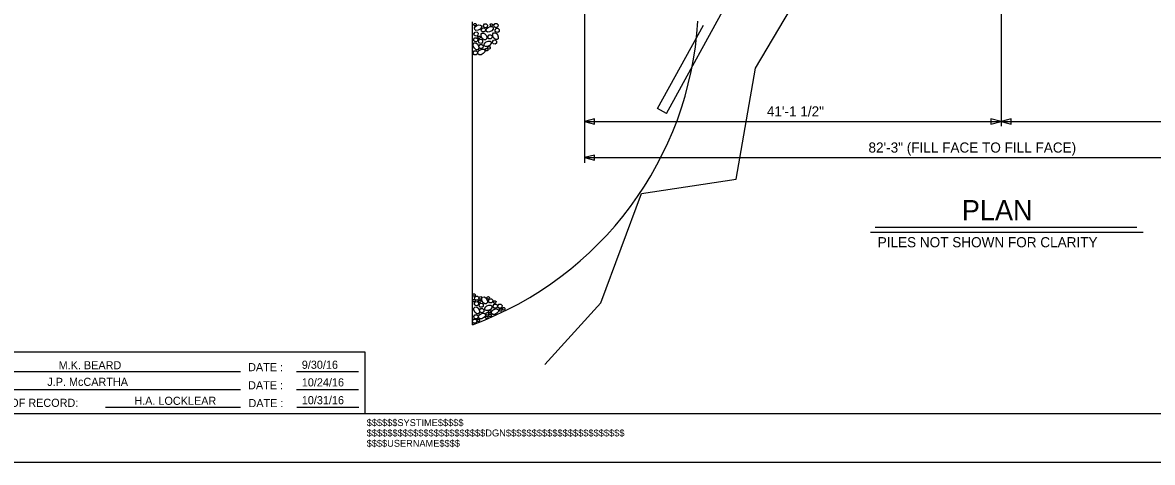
# Model space of a CAD drawing. Extents: x 471 to 2034, y -623 to 126.
# Drawn here: x 1490.5 to 1602, y -95.1 to -51.7 of the extents above; entities that cross this region are included whole.
import ezdxf

# ---------------------------------------------------------------- set-up
doc = ezdxf.new("R2010")
doc.units = 0
for name, color, linetype in [('Auto Dimensioning', 7, 'Continuous'), ('Dimension Lines', 7, 'Continuous'), ('Exist Hydro Stream or Body of Water', 7, 'Continuous'), ('Exist Structure Major Bridge Seam', 7, 'Continuous'), ('Miscellaneous Lines CELL', 7, 'Continuous'), ('Plan Sheet CELL', 7, 'Continuous'), ('Plot Label CELL', 7, 'Continuous'), ('Plot Shape CELL', 7, 'Continuous'), ('Sub End Bent Cap Lines CELL', 7, 'Continuous'), ('Subtitle Text', 7, 'Continuous'), ('Sup Concrete Girder Lines', 7, 'Continuous'), ('Text', 7, 'Continuous'), ('Title Text', 7, 'Continuous')]:
    doc.layers.add(name, color=color, linetype=linetype)

# ---------------------------------------------------------------- blocks, each defined once
blk = doc.blocks.new('AH')
at = {"layer": 'Sub End Bent Cap Lines CELL'}
blk.add_lwpolyline([(0, 0), (-1.25, 0.31), (-1.25, -0.31)], close=True, dxfattribs=at)

msp = doc.modelspace()

# ---------------------------------------------------------------- linework, layer by layer
at = {"layer": 'Auto Dimensioning'}
for p, q in [((1545.96, -33.72), (1545.96, -65.55)), ((1545.96, -61.48), (1587.08, -61.48)), ((1587.08, -61.48), (1628.19, -61.48)), ((1545.96, -65.05), (1628.19, -65.05))]:
    msp.add_line(p, q, dxfattribs=at)
at = {"layer": 'Dimension Lines'}
msp.add_line((1587.08, -33.22), (1587.08, -61.95), dxfattribs=at)
at = {"layer": 'Exist Hydro Stream or Body of Water'}
for points in [[(1562.84, -56.21), (1566.3, -50.38), (1560.81, -40.91)], [(1542.05, -85.49), (1547.57, -79.39), (1551.61, -68.59), (1560.94, -67.16), (1562.84, -56.21)]]:
    msp.add_lwpolyline(points, dxfattribs=at)
at = {"layer": 'Exist Structure Major Bridge Seam'}
for p, q in [((1554.07, -60.68), (1560.64, -48.7)), ((1553.19, -60.2), (1557.72, -51.96)), ((1554.07, -60.68), (1553.19, -60.2))]:
    msp.add_line(p, q, dxfattribs=at)
at = {"layer": 'Miscellaneous Lines CELL'}
for points in [[(1535.03, -51.89), (1535.1, -51.79), (1535.21, -51.79), (1535.28, -51.86), (1535.27, -51.97), (1535.2, -52.03), (1535.1, -52.02), (1535.05, -51.97), (1535.03, -51.89)], [(1535.32, -52.01), (1535.53, -51.93), (1535.72, -51.95), (1535.82, -52.03), (1535.81, -52.19), (1535.67, -52.37), (1535.46, -52.47), (1535.26, -52.48), (1535.14, -52.4), (1535.13, -52.23), (1535.22, -52.09), (1535.33, -52.01)], [(1535.78, -52.41), (1535.89, -52.25), (1536.07, -52.24), (1536.19, -52.37), (1536.17, -52.55), (1536.06, -52.64), (1535.89, -52.63), (1535.8, -52.55), (1535.78, -52.41)], [(1535.99, -51.99), (1536.1, -51.83), (1536.28, -51.82), (1536.4, -51.95), (1536.38, -52.13), (1536.27, -52.22), (1536.1, -52.21), (1536.01, -52.13), (1535.99, -51.99)], [(1536.46, -52.18), (1536.67, -52.1), (1536.86, -52.11), (1536.95, -52.2), (1536.95, -52.36), (1536.81, -52.54), (1536.6, -52.64), (1536.4, -52.65), (1536.28, -52.57), (1536.27, -52.4), (1536.36, -52.26), (1536.47, -52.18)], [(1536.67, -51.93), (1536.73, -51.83), (1536.84, -51.82), (1536.92, -51.9), (1536.9, -52.01), (1536.84, -52.06), (1536.73, -52.06), (1536.68, -52.01), (1536.67, -51.93)], [(1537.03, -51.97), (1537.15, -51.81), (1537.32, -51.8), (1537.45, -51.93), (1537.43, -52.11), (1537.32, -52.2), (1537.14, -52.19), (1537.06, -52.11), (1537.03, -51.97)], [(1537.14, -52.44), (1537.25, -52.28), (1537.43, -52.27), (1537.55, -52.4), (1537.54, -52.58), (1537.43, -52.68), (1537.25, -52.66), (1537.17, -52.58), (1537.14, -52.44)], [(1535.03, -53.37), (1535.14, -53.21), (1535.32, -53.2), (1535.44, -53.33), (1535.42, -53.51), (1535.31, -53.6), (1535.14, -53.59), (1535.05, -53.5), (1535.03, -53.37)], [(1535.06, -52.81), (1535.17, -52.65), (1535.35, -52.64), (1535.47, -52.77), (1535.45, -52.95), (1535.34, -53.04), (1535.17, -53.03), (1535.08, -52.95), (1535.06, -52.81)], [(1535.44, -53.14), (1535.51, -53.04), (1535.62, -53.04), (1535.69, -53.11), (1535.68, -53.22), (1535.61, -53.28), (1535.51, -53.27), (1535.46, -53.22), (1535.44, -53.14)], [(1535.5, -53.52), (1535.61, -53.37), (1535.79, -53.35), (1535.91, -53.48), (1535.9, -53.66), (1535.79, -53.76), (1535.61, -53.74), (1535.53, -53.66), (1535.5, -53.52)], [(1536.23, -52.93), (1536.32, -53.13), (1536.3, -53.33), (1536.21, -53.42), (1536.06, -53.42), (1535.88, -53.28), (1535.77, -53.06), (1535.77, -52.86), (1535.85, -52.75), (1536.01, -52.74), (1536.15, -52.83), (1536.24, -52.93)], [(1536.43, -53.08), (1536.55, -52.92), (1536.73, -52.91), (1536.85, -53.04), (1536.83, -53.22), (1536.72, -53.32), (1536.54, -53.3), (1536.46, -53.22), (1536.43, -53.08)], [(1536.88, -53.6), (1536.99, -53.44), (1537.17, -53.43), (1537.3, -53.56), (1537.28, -53.74), (1537.17, -53.84), (1536.99, -53.82), (1536.91, -53.74), (1536.88, -53.6)], [(1537.37, -52.9), (1537.45, -53.11), (1537.44, -53.3), (1537.35, -53.39), (1537.19, -53.39), (1537.02, -53.25), (1536.91, -53.04), (1536.91, -52.83), (1536.99, -52.72), (1537.15, -52.71), (1537.29, -52.8), (1537.38, -52.91)], [(1534.98, -54.67), (1535.09, -54.51), (1535.27, -54.5), (1535.4, -54.62), (1535.38, -54.81), (1535.27, -54.9), (1535.09, -54.88), (1535.01, -54.8), (1534.98, -54.67)], [(1535.45, -53.9), (1535.54, -54.11), (1535.52, -54.3), (1535.43, -54.4), (1535.28, -54.39), (1535.1, -54.25), (1534.99, -54.04), (1534.99, -53.84), (1535.07, -53.72), (1535.23, -53.71), (1535.37, -53.8), (1535.46, -53.91)], [(1535.63, -54.42), (1535.84, -54.34), (1536.03, -54.35), (1536.12, -54.44), (1536.12, -54.6), (1535.98, -54.77), (1535.76, -54.88), (1535.56, -54.88), (1535.45, -54.8), (1535.44, -54.64), (1535.53, -54.5), (1535.64, -54.41)], [(1535.55, -54.05), (1535.66, -53.89), (1535.84, -53.88), (1535.96, -54.01), (1535.95, -54.19), (1535.84, -54.28), (1535.66, -54.27), (1535.58, -54.19), (1535.55, -54.05)], [(1536.26, -53.62), (1536.47, -53.53), (1536.66, -53.55), (1536.75, -53.64), (1536.75, -53.79), (1536.61, -53.97), (1536.39, -54.08), (1536.19, -54.08), (1536.08, -54), (1536.07, -53.84), (1536.16, -53.7), (1536.27, -53.61)], [(1536.18, -54.37), (1536.24, -54.28), (1536.35, -54.27), (1536.43, -54.35), (1536.42, -54.46), (1536.35, -54.51), (1536.24, -54.51), (1536.19, -54.46), (1536.18, -54.37)], [(1536.41, -54.18), (1536.48, -54.08), (1536.58, -54.08), (1536.66, -54.16), (1536.65, -54.26), (1536.58, -54.32), (1536.47, -54.31), (1536.42, -54.26), (1536.41, -54.18)], [(1534.93, -78.59), (1535, -78.49), (1535.11, -78.49), (1535.18, -78.56), (1535.17, -78.67), (1535.11, -78.73), (1535, -78.72), (1534.95, -78.67), (1534.93, -78.59)], [(1534.93, -79.15), (1535, -79.06), (1535.11, -79.05), (1535.18, -79.13), (1535.17, -79.24), (1535.11, -79.29), (1535, -79.29), (1534.95, -79.24), (1534.93, -79.15)], [(1535.13, -78.89), (1535.24, -78.73), (1535.42, -78.72), (1535.54, -78.85), (1535.52, -79.03), (1535.41, -79.12), (1535.24, -79.11), (1535.15, -79.03), (1535.13, -78.89)], [(1535.51, -79.21), (1535.58, -79.12), (1535.69, -79.11), (1535.76, -79.19), (1535.75, -79.3), (1535.68, -79.35), (1535.58, -79.35), (1535.53, -79.3), (1535.51, -79.21)], [(1535.57, -78.87), (1535.64, -78.78), (1535.74, -78.77), (1535.82, -78.85), (1535.81, -78.96), (1535.74, -79.01), (1535.63, -79.01), (1535.58, -78.96), (1535.57, -78.87)], [(1536.3, -79), (1536.39, -79.21), (1536.37, -79.4), (1536.28, -79.49), (1536.13, -79.49), (1535.95, -79.35), (1535.84, -79.14), (1535.84, -78.93), (1535.92, -78.82), (1536.08, -78.81), (1536.22, -78.9), (1536.31, -79.01)], [(1536.33, -78.87), (1536.4, -78.78), (1536.51, -78.77), (1536.58, -78.85), (1536.57, -78.96), (1536.5, -79.01), (1536.4, -79.01), (1536.35, -78.96), (1536.33, -78.87)], [(1536.5, -79.16), (1536.62, -79), (1536.79, -78.99), (1536.92, -79.12), (1536.9, -79.3), (1536.79, -79.39), (1536.61, -79.38), (1536.53, -79.3), (1536.5, -79.16)], [(1535.52, -79.98), (1535.61, -80.19), (1535.59, -80.38), (1535.5, -80.47), (1535.35, -80.47), (1535.17, -80.33), (1535.06, -80.11), (1535.06, -79.91), (1535.14, -79.8), (1535.3, -79.79), (1535.44, -79.88), (1535.53, -79.98)], [(1535.09, -79.44), (1535.21, -79.28), (1535.39, -79.27), (1535.51, -79.4), (1535.49, -79.58), (1535.38, -79.67), (1535.21, -79.66), (1535.12, -79.58), (1535.1, -79.44)], [(1535.57, -79.6), (1535.68, -79.44), (1535.86, -79.43), (1535.98, -79.56), (1535.97, -79.74), (1535.86, -79.83), (1535.68, -79.82), (1535.6, -79.74), (1535.57, -79.6)], [(1535.62, -80.12), (1535.73, -79.96), (1535.91, -79.95), (1536.03, -80.08), (1536.02, -80.26), (1535.9, -80.36), (1535.73, -80.34), (1535.65, -80.26), (1535.62, -80.12)], [(1536.33, -79.69), (1536.54, -79.61), (1536.73, -79.63), (1536.82, -79.71), (1536.82, -79.87), (1536.68, -80.05), (1536.46, -80.15), (1536.26, -80.16), (1536.15, -80.08), (1536.14, -79.92), (1536.23, -79.77), (1536.34, -79.69)], [(1536.48, -80.25), (1536.55, -80.16), (1536.65, -80.15), (1536.73, -80.23), (1536.72, -80.34), (1536.65, -80.39), (1536.54, -80.39), (1536.49, -80.34), (1536.48, -80.25)], [(1536.98, -80.07), (1537.19, -79.98), (1537.38, -80), (1537.47, -80.09), (1537.47, -80.24), (1537.33, -80.42), (1537.11, -80.53), (1536.91, -80.53), (1536.8, -80.45), (1536.79, -80.29), (1536.88, -80.15), (1536.99, -80.06)], [(1536.95, -79.68), (1537.06, -79.52), (1537.24, -79.51), (1537.37, -79.64), (1537.35, -79.82), (1537.24, -79.91), (1537.06, -79.9), (1536.98, -79.82), (1536.95, -79.68)], [(1536.99, -79.29), (1537.05, -79.19), (1537.16, -79.18), (1537.24, -79.26), (1537.23, -79.37), (1537.16, -79.43), (1537.05, -79.42), (1537, -79.37), (1536.99, -79.29)], [(1537.41, -79.68), (1537.53, -79.53), (1537.7, -79.52), (1537.83, -79.64), (1537.81, -79.82), (1537.7, -79.92), (1537.52, -79.9), (1537.44, -79.82), (1537.41, -79.68)], [(1537.58, -80.07), (1537.64, -79.97), (1537.75, -79.97), (1537.83, -80.05), (1537.81, -80.15), (1537.75, -80.21), (1537.64, -80.2), (1537.59, -80.15), (1537.58, -80.07)], [(1537.87, -79.96), (1537.94, -79.86), (1538.05, -79.86), (1538.12, -79.93), (1538.11, -80.04), (1538.05, -80.1), (1537.94, -80.09), (1537.89, -80.04), (1537.87, -79.96)], [(1534.92, -81.17), (1535.03, -81.01), (1535.21, -81), (1535.34, -81.13), (1535.32, -81.31), (1535.21, -81.41), (1535.03, -81.39), (1534.95, -81.31), (1534.92, -81.17)], [(1535.05, -80.74), (1535.16, -80.58), (1535.34, -80.57), (1535.47, -80.7), (1535.45, -80.88), (1535.34, -80.97), (1535.16, -80.96), (1535.08, -80.88), (1535.05, -80.74)], [(1535.37, -81.09), (1535.44, -80.99), (1535.54, -80.99), (1535.62, -81.07), (1535.61, -81.17), (1535.54, -81.23), (1535.44, -81.22), (1535.39, -81.17), (1535.37, -81.09)], [(1535.7, -80.49), (1535.91, -80.41), (1536.1, -80.43), (1536.19, -80.51), (1536.19, -80.67), (1536.05, -80.85), (1535.83, -80.96), (1535.63, -80.96), (1535.52, -80.88), (1535.51, -80.72), (1535.6, -80.57), (1535.7, -80.49)], [(1536.19, -80.79), (1536.26, -80.69), (1536.37, -80.69), (1536.44, -80.76), (1536.43, -80.87), (1536.37, -80.93), (1536.26, -80.92), (1536.21, -80.87), (1536.19, -80.79)], [(1536.25, -80.45), (1536.31, -80.35), (1536.42, -80.35), (1536.5, -80.42), (1536.49, -80.53), (1536.42, -80.59), (1536.31, -80.58), (1536.26, -80.53), (1536.25, -80.45)], [(1536.51, -80.61), (1536.58, -80.51), (1536.68, -80.5), (1536.76, -80.58), (1536.75, -80.69), (1536.68, -80.74), (1536.57, -80.74), (1536.52, -80.69), (1536.51, -80.61)]]:
    msp.add_lwpolyline(points, dxfattribs=at)
at = {"layer": 'Plan Sheet CELL'}
for p, q in [((1478.11, -84.21), (1524.3, -84.21)), ((1524.3, -84.21), (1524.3, -90.3)), ((1487.06, -86.18), (1512.03, -86.18)), ((1517.53, -86.18), (1523.65, -86.18)), ((1488.2, -87.94), (1512.03, -87.94)), ((1517.53, -87.94), (1523.65, -87.94)), ((1478.11, -90.3), (1734.11, -90.3)), ((1498.69, -89.69), (1512.03, -89.69)), ((1498.69, -89.69), (1512.03, -89.69)), ((1517.57, -89.69), (1523.69, -89.69)), ((1517.57, -89.69), (1523.69, -89.69))]:
    msp.add_line(p, q, dxfattribs=at)
at = {"layer": 'Plot Shape CELL'}
msp.add_lwpolyline([(1469.68, 80.85), (1734.18, 80.85), (1734.18, -95.15), (1469.68, -95.15)], close=True, dxfattribs=at)
at = {"layer": 'Sup Concrete Girder Lines'}
msp.add_line((1534.91, -81.55), (1534.91, -51.63), dxfattribs=at)
msp.add_arc((1523.18, -49.6), 34.03, 290.162, 356.6744, dxfattribs=at)
at = {"layer": 'Title Text'}
for p, q in [((1574.2, -72.4), (1601.11, -72.4)), ((1574.65, -71.9), (1600.49, -71.9))]:
    msp.add_line(p, q, dxfattribs=at)

# ---------------------------------------------------------------- block references
at = {"layer": 'Auto Dimensioning', "xscale": 0.8, "yscale": 0.8000000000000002, "rotation": 180}
for p in [(1545.96, -61.48), (1587.08, -61.48), (1545.96, -65.05)]:
    msp.add_blockref('AH', p, dxfattribs=at)
at = {"layer": 'Auto Dimensioning', "xscale": 0.8, "yscale": 0.8000000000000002}
msp.add_blockref('AH', (1587.08, -61.48), dxfattribs=at)

# ---------------------------------------------------------------- texts
at = {"layer": 'Plan Sheet CELL'}
for s, p in [('DATE :', (1512.77, -86.14)), ('DATE :', (1512.77, -87.93)), ('DESIGN ENGINEER OF RECORD:', (1479.01, -89.66)), ('DATE :', (1512.81, -89.69))]:
    msp.add_text(s, height=0.8, dxfattribs=at).set_placement(p)
at = {"layer": 'Plot Label CELL'}
for s, height, p in [('$$$$$$SYSTIME$$$$$', 0.6803, (1524.47, -91.56)), ('$$$$$$$$$$$$$$$$$$$$$$$DGN$$$$$$$$$$$$$$$$$$$$$$$', 0.6845, (1524.47, -92.58)), ('$$$$USERNAME$$$$', 0.6803, (1524.47, -93.6))]:
    msp.add_text(s, height=height, dxfattribs=at).set_placement(p)
at = {"layer": 'Subtitle Text'}
for s, p in [('M.K. BEARD', (1494.07, -85.95)), ('9/30/16', (1518.07, -85.9)), ('J.P. McCARTHA', (1492.95, -87.59)), ('10/24/16', (1518.07, -87.64)), ('H.A. LOCKLEAR', (1501.54, -89.46)), ('10/31/16', (1518.07, -89.4))]:
    msp.add_text(s, height=0.8, dxfattribs=at).set_placement(p)
at = {"layer": 'Text'}
for s, p in [('41\'-1 1/2"', (1563.97, -60.98)), ('82\'-3" (FILL FACE TO FILL FACE)', (1574, -64.55)), ('PILES NOT SHOWN FOR CLARITY', (1574.91, -73.9))]:
    msp.add_text(s, height=1, dxfattribs=at).set_placement(p)
at = {"layer": 'Title Text'}
msp.add_text('PLAN', height=2, dxfattribs=at).set_placement((1583.21, -71.24))

doc.saveas('drawing.dxf')
